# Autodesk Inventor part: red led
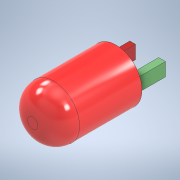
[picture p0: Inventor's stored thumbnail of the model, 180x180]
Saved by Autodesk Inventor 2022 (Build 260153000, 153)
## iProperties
Created: 2021-06
Part Number: red led
Material: Generic
Document SubType Name: Modeling
Designer: Dell
Density: 1 g/cm^3
Appearance: Default
Author: Dell
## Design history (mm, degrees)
sketch "Sketch1"
  geometry: C1 r 2.5 at (0, 0); 1 further point
  constraints: 1 centre point, 1 coincident
  dimensions: "d0" = 5 diameter of C1
extrude "Extrusion1" new body sketch "Sketch1" distance "d1" = 8; taper "d2" = 0 deg
fillet "Fillet1" dims "d3" = 2
sketch "Sketch2"
  geometry: L1 (1.668, 0.5)-(1.114, 0.5); L2 (1.114, 0.5)-(1.114, -0.783); L3 (1.114, -0.783)-(1.668, -0.783); L4 (1.668, -0.783)-(1.668, 0.5); L5 (-1.096, 0.5)-(-1.755, 0.5); L6 (-1.755, 0.5)-(-1.755, -0.783); L7 (-1.755, -0.783)-(-1.096, -0.783); L8 (-1.096, -0.783)-(-1.096, 0.5); 1 further point
  constraints: 16 end point, 4 parallel, 2 horizontal, 2 perpendicular, 2 point on line
extrude "Extrusion2" join sketch "Sketch2" distance "d4" = 3; taper "d5" = 0 deg
body "Solid1"
